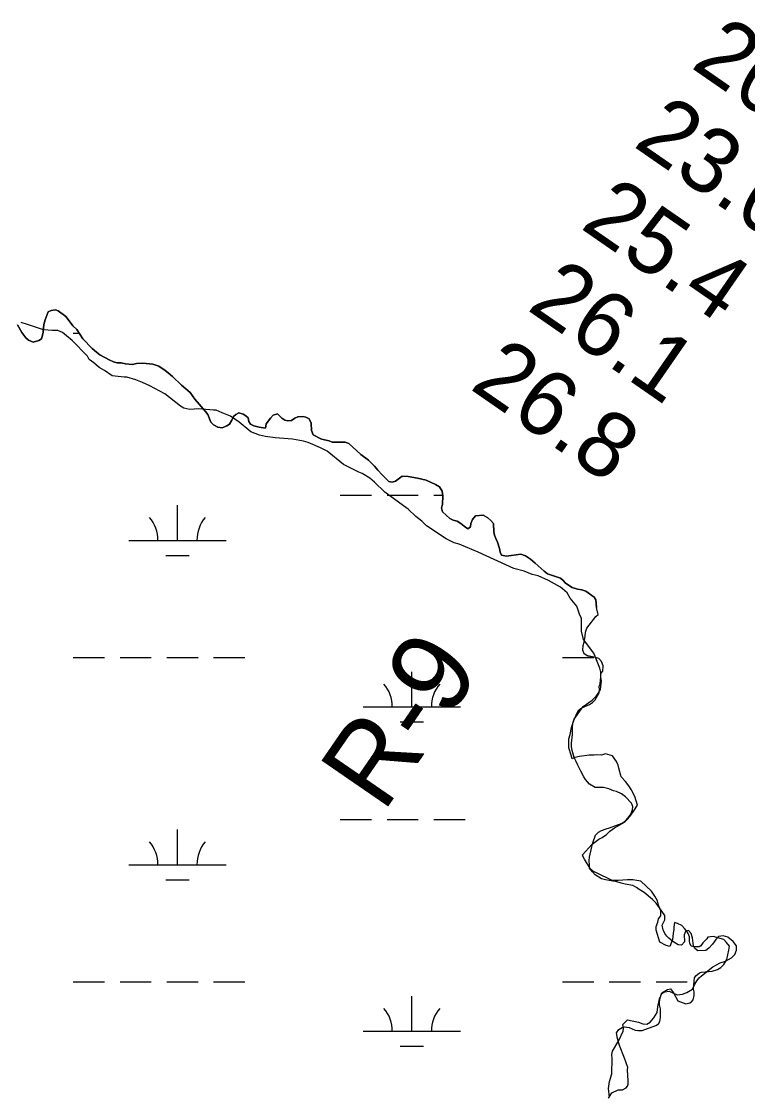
# Model space of a CAD drawing. Extents: x 3192927 to 3230760, y 831141 to 856475.
# Drawn here: x 3204190 to 3204934, y 850320 to 851421 of the extents above; entities that cross this region are included whole.
import ezdxf

# ---------------------------------------------------------------- set-up
doc = ezdxf.new("R2010")
doc.units = 0
for name, color, linetype in [('V-RIVR-RANG', 7, 'Continuous'), ('V-RIVR-RANG-IDEN', 7, 'Continuous'), ('V-SITE-VEGE', 7, 'Continuous'), ('V-TOPO-SHOR', 7, 'Continuous'), ('V-WETL-SWMP', 7, 'Continuous')]:
    doc.layers.add(name, color=color, linetype=linetype)

msp = doc.modelspace()

# ---------------------------------------------------------------- linework, layer by layer
at = {"layer": 'V-SITE-VEGE'}
for points in [[(3204356.3, 851024.6), (3204352.9, 851026.6), (3204336.8, 851039.5), (3204321.3, 851047.6), (3204313.8, 851051), (3204307.1, 851053.7), (3204297.7, 851056.4), (3204295, 851056.4), (3204282.8, 851057.8), (3204274.7, 851063.2), (3204269.4, 851066.5), (3204264, 851071.3), (3204259.2, 851074.7), (3204257.2, 851078), (3204241.7, 851094.2), (3204235.7, 851099), (3204231.6, 851102.4), (3204226.9, 851104.4), (3204221.5, 851104.4), (3204212.1, 851105.1), (3204195.9, 851110.5), (3204189.2, 851112.5)], [(3204799.1, 850540), (3204794.8, 850540.4), (3204780.2, 850547.7), (3204776.3, 850549.5), (3204772.9, 850552.5), (3204767.3, 850561.9), (3204765.6, 850564.5), (3204765.2, 850566.6), (3204775.1, 850577.4), (3204782, 850582.5), (3204785.4, 850584.2), (3204789.7, 850587.2), (3204793.1, 850590.6), (3204797.9, 850594.1), (3204808.2, 850600), (3204811.6, 850603.5), (3204814.6, 850607.3), (3204817.6, 850611.6), (3204821.5, 850617.6), (3204818.9, 850626.2), (3204815.1, 850633.5), (3204812.5, 850637.4), (3204809.1, 850641.7), (3204804.8, 850646.4), (3204802.2, 850655.4), (3204801.8, 850658.4), (3204800.1, 850662.3), (3204795.8, 850667.9), (3204788.5, 850670), (3204784.7, 850668.7), (3204779.5, 850669.2), (3204777, 850668.8), (3204771.8, 850668.8), (3204761.9, 850667.5), (3204757.2, 850666.2), (3204754.6, 850664.9), (3204753.4, 850668.8), (3204751.2, 850676.1), (3204751.2, 850685.5), (3204752.5, 850689.8), (3204753.8, 850697.1), (3204756.4, 850705.7), (3204765.9, 850718.5), (3204771.5, 850722.8), (3204774.9, 850725), (3204779.2, 850729.2), (3204781.3, 850731.8), (3204783.5, 850736.1), (3204783.9, 850739.1), (3204784.4, 850744.7), (3204783.9, 850748.6), (3204784, 850753.7), (3204782.7, 850758), (3204776.7, 850773.5), (3204766, 850787.2), (3204764, 850796), (3204764, 850808.8), (3204762, 850813.5), (3204759.3, 850821.6), (3204752.6, 850829.7), (3204749.2, 850835.1), (3204744.5, 850839.2), (3204742.5, 850841.2), (3204730.3, 850848), (3204719.5, 850852.7), (3204713.5, 850854.1), (3204705.4, 850857.4), (3204694.6, 850860.2), (3204658.2, 850877.1), (3204638.7, 850885.2), (3204633.3, 850886.6), (3204625.2, 850890.6), (3204605, 850904.1), (3204600.3, 850908.9), (3204594.2, 850913.6), (3204586.1, 850921), (3204581.4, 850924.4), (3204562.5, 850938.6), (3204551.8, 850948.7), (3204547, 850952.8), (3204539, 850957.5), (3204535.6, 850958.9), (3204520.1, 850967), (3204503.3, 850980.5), (3204496.5, 850983.9), (3204483.7, 850989.3), (3204479, 850990.7), (3204467.5, 850992.7), (3204450, 850994.1), (3204439.9, 850995.5), (3204433.8, 850996.8), (3204425, 851000.2), (3204423, 851002.2), (3204412.9, 851010.3), (3204404.2, 851016.4), (3204395.4, 851019.8), (3204389.3, 851022.5), (3204386.6, 851022.5), (3204371.1, 851023.9), (3204362.4, 851023.2), (3204356.3, 851024.6)], [(3204791.8, 850316.9), (3204795.3, 850322.4), (3204801.7, 850325.4), (3204806, 850325.4), (3204809.9, 850327.6), (3204811.2, 850329.3), (3204812, 850331.4), (3204812, 850334.8), (3204811.2, 850346), (3204811.6, 850348.2), (3204808.2, 850358), (3204803.1, 850370.9), (3204800.9, 850378.2), (3204800.1, 850383.8), (3204802.2, 850387.2), (3204805.7, 850389.4), (3204808.3, 850390.2), (3204813, 850389.3), (3204819, 850386.8), (3204822, 850386.3), (3204826.3, 850386.3), (3204840.4, 850391.4), (3204843, 850393.2), (3204844.3, 850395.7), (3204845.2, 850399.6), (3204845.2, 850408.6), (3204843.9, 850412.5), (3204843.9, 850415.5), (3204844.8, 850419.8), (3204846.5, 850424.9), (3204852.1, 850428.3), (3204855.5, 850429.2), (3204858.5, 850424.9), (3204862.8, 850416.7), (3204870.9, 850413.7), (3204875.2, 850414.6), (3204877, 850415.8), (3204878.7, 850417.6), (3204879.5, 850422.3), (3204879.5, 850426.1), (3204879.1, 850428.7), (3204879.6, 850436.9), (3204880, 850440.3), (3204881.3, 850442.4), (3204885.2, 850445.4), (3204887.3, 850446.3), (3204898, 850447.1), (3204903.6, 850448.8), (3204907.1, 850451), (3204910.1, 850454), (3204913.1, 850459.1), (3204915.2, 850468.6), (3204915.7, 850472.9), (3204912.7, 850476.7), (3204910.1, 850479.7), (3204899, 850482.8), (3204893.8, 850481.9), (3204892.5, 850480.2), (3204888.6, 850476.3), (3204886.5, 850473.3), (3204884.8, 850472), (3204879.2, 850472.1), (3204876.6, 850472.9), (3204875.3, 850475.9), (3204874.9, 850478.1), (3204874.9, 850482.4), (3204873.6, 850485.8), (3204871.9, 850488.4), (3204869.8, 850491), (3204866.8, 850494), (3204862.5, 850496.1), (3204859.5, 850497), (3204858.6, 850492.3), (3204858.6, 850490.1), (3204858.2, 850485.8), (3204857.3, 850479.8), (3204854.7, 850472.5), (3204850.9, 850473.4), (3204844.4, 850476.8), (3204840.6, 850489.3), (3204840.6, 850493.1), (3204842.3, 850497.4), (3204843.2, 850500.9), (3204845.3, 850503.9), (3204845.4, 850509), (3204843.2, 850515), (3204841.9, 850519.3), (3204839.4, 850524), (3204835.9, 850529.2), (3204824.8, 850539.5), (3204816.7, 850540.8), (3204811.1, 850540.8), (3204801.6, 850540), (3204799.1, 850540)]]:
    msp.add_lwpolyline(points, dxfattribs=at)
at = {"layer": 'V-TOPO-SHOR'}
for points in [[(3204185.6, 851110.2), (3204190, 851102.3), (3204194, 851096.7), (3204197, 851094.3), (3204201.7, 851092.2), (3204207.3, 851094.1), (3204210.1, 851095.9), (3204211.3, 851099.4), (3204212, 851102.5), (3204212.2, 851106.7), (3204212.7, 851110.6), (3204214.1, 851115.1), (3204217.1, 851123.5), (3204220, 851124.9), (3204224.4, 851125.6), (3204227.2, 851124.4), (3204235.1, 851118.8), (3204238.6, 851114.3), (3204242.3, 851109.2), (3204246.5, 851105.2), (3204252.4, 851095.9), (3204262.2, 851086), (3204266.6, 851082.1), (3204269.9, 851079.5), (3204279.7, 851074.1), (3204284.1, 851072.2), (3204287.8, 851071.3), (3204291.8, 851071.1), (3204296.2, 851070.1), (3204303.5, 851069.6), (3204307.7, 851070.3), (3204313.3, 851070.8), (3204317.5, 851070.5), (3204324.3, 851069.8), (3204330.6, 851067.7), (3204337.1, 851063.3), (3204340.1, 851060.9), (3204344.6, 851057.2), (3204353.9, 851048.1), (3204362.5, 851040.8), (3204367.6, 851033.8), (3204378.4, 851021.2), (3204380.7, 851018.1), (3204383.9, 851010.2), (3204386.7, 851007.4), (3204390.9, 851005.3), (3204395.4, 851004.3), (3204400.3, 851006.4), (3204403.1, 851008.3), (3204405.4, 851012.5), (3204407.1, 851016.2), (3204409.6, 851018.3), (3204412.5, 851019.7), (3204416.9, 851018.5), (3204419.7, 851016.9), (3204422, 851014.6), (3204423, 851010.8), (3204424.6, 851008.3), (3204428.1, 851006.6), (3204433.5, 851005.2), (3204440, 851004), (3204440.5, 851008.5), (3204444.9, 851014.3), (3204447.9, 851017.6), (3204452.4, 851019), (3204456.8, 851014.3), (3204459.6, 851012.2), (3204462.9, 851011.5), (3204466.6, 851011.9), (3204469.9, 851014.3), (3204473.2, 851015.9), (3204478.1, 851016.1), (3204481.3, 851015.4), (3204484.6, 851013.8), (3204486.9, 851009.3), (3204487.2, 851001.8), (3204488.8, 850997.4), (3204497.2, 850992.7), (3204505.1, 850991.1), (3204508.4, 850989.9), (3204516.8, 850989.9), (3204521.7, 850989.6), (3204525.4, 850988.5), (3204537.6, 850977), (3204545.5, 850971.2), (3204551.8, 850965.3), (3204555.3, 850961.1), (3204559.5, 850956.4), (3204566.5, 850949.4), (3204570, 850948.7), (3204573.2, 850949.6), (3204580, 850954.8), (3204586.3, 850954.5), (3204595.9, 850952.9)], [(3204595.9, 850952.9), (3204604.8, 850950.7), (3204614.3, 850946.3), (3204618.3, 850944), (3204621.1, 850939.5), (3204621.8, 850934.8), (3204621.6, 850926), (3204620.6, 850922.5), (3204621.5, 850918.3), (3204629, 850911.5), (3204632.5, 850909.8), (3204636.5, 850908.7), (3204640.4, 850906.3), (3204643.7, 850903.5), (3204647.4, 850900.9), (3204650.2, 850903), (3204650.7, 850906.5), (3204652.4, 850910.3), (3204655.2, 850914.2), (3204663.3, 850914.9), (3204668, 850912.3), (3204671, 850909.5), (3204673.8, 850906.5), (3204674.3, 850897.9), (3204674.7, 850894.4), (3204676.1, 850890.8), (3204678, 850887.1), (3204680.1, 850880.8), (3204680.6, 850877.1), (3204682, 850874), (3204687.1, 850872.8), (3204701.8, 850874.9), (3204706.5, 850873.3), (3204711.8, 850869.8), (3204716.5, 850865.8), (3204725.6, 850857.4), (3204729.3, 850854.6), (3204742.4, 850850.1), (3204745.4, 850847.8), (3204747.8, 850845), (3204754.5, 850840.7), (3204760.1, 850838.9), (3204764.3, 850838.4), (3204768.5, 850837), (3204776.9, 850830.7), (3204778.6, 850827.9), (3204779.5, 850820.2)], [(3204754.4, 850673.4), (3204753.8, 850677.3), (3204753.9, 850680.9), (3204754.8, 850690), (3204754.8, 850696.9), (3204755.3, 850701.5), (3204756.9, 850706), (3204759.2, 850711.4), (3204761.3, 850715.3), (3204764.3, 850717.4), (3204772.3, 850720.8), (3204775.3, 850722.7), (3204778, 850725.4), (3204782.2, 850732.6), (3204782.6, 850735.6), (3204782.2, 850739.1), (3204783.3, 850742), (3204784, 850749.2), (3204784, 850752.4), (3204785.8, 850754.9), (3204786.3, 850760.2), (3204784.4, 850764.9), (3204781.9, 850767.8), (3204778.4, 850769), (3204770.4, 850770.5), (3204766.9, 850772.8), (3204765.3, 850776.3), (3204765.7, 850781.1), (3204766.7, 850784.6), (3204767.8, 850790.4), (3204768.2, 850794.8), (3204769.4, 850798.9), (3204774.2, 850805.1), (3204776.2, 850807.9), (3204778.8, 850810.9), (3204781.1, 850812.9), (3204779.5, 850820.2)], [(3204822.5, 850394.7), (3204826.8, 850393.3), (3204831.2, 850392.8), (3204834.4, 850394.7), (3204838.4, 850399.3), (3204841.6, 850404.8), (3204842.5, 850410.6), (3204844.1, 850418.9), (3204846.4, 850424.2), (3204849.4, 850426.1), (3204853.9, 850426.7), (3204862.2, 850422.9), (3204867.6, 850423.5), (3204872.2, 850425.4), (3204877.9, 850428.8), (3204880.2, 850433.7), (3204882.5, 850437.4), (3204884.6, 850440.4), (3204887.1, 850442.5), (3204898.8, 850451.5), (3204906.4, 850455.8), (3204911.9, 850457.5), (3204917.9, 850460.7), (3204921.3, 850464.2), (3204923.2, 850468.6), (3204923.2, 850473.2), (3204919.7, 850477.5), (3204914.2, 850481.9), (3204909.5, 850483.5), (3204904.7, 850482.8), (3204901.8, 850479.6), (3204898.3, 850474.7), (3204894.8, 850470.8), (3204891.6, 850468.3), (3204883.3, 850468), (3204880.4, 850470.5), (3204879, 850473.1), (3204878, 850481.4), (3204876.4, 850485.9), (3204873.8, 850489), (3204870.6, 850488), (3204869.5, 850484.4), (3204869.8, 850477.4), (3204866.5, 850473.7), (3204863.3, 850474.2), (3204857.6, 850477.6), (3204853.8, 850480.9), (3204851.6, 850483.2), (3204849.7, 850485.9), (3204847.8, 850489.6), (3204846.7, 850494.4), (3204849.7, 850499.7), (3204849.4, 850504.1), (3204846.6, 850508.7), (3204840.6, 850517), (3204836.9, 850520.6), (3204828.2, 850527.8), (3204823.3, 850530.8), (3204820.3, 850533.1), (3204816.6, 850535.1), (3204808.8, 850536.5), (3204804.9, 850537.4), (3204799.1, 850539), (3204796.1, 850539.4), (3204788.8, 850541), (3204784.7, 850542), (3204778, 850545.9), (3204775.2, 850548.9), (3204772.2, 850552.7), (3204772.2, 850556), (3204771.9, 850560.8), (3204772.2, 850564.2), (3204774.5, 850574.8), (3204775.6, 850578.8), (3204778.5, 850586.8), (3204781.5, 850589.8), (3204784.5, 850591.4), (3204789.2, 850593.1), (3204792.8, 850594.2), (3204805.9, 850599.1), (3204809.6, 850601.6), (3204811.7, 850604), (3204814.5, 850608.1), (3204816.5, 850612.5), (3204816.7, 850616.2), (3204815.3, 850619.4), (3204809.3, 850626.1), (3204805, 850629), (3204799.9, 850631.5), (3204796.9, 850632.3), (3204792, 850634.1), (3204786.7, 850635.4), (3204778.2, 850635.6), (3204772.2, 850638.9), (3204768.3, 850643.7), (3204766.5, 850646.4), (3204763.5, 850652.4), (3204760.2, 850658.4), (3204758.1, 850662.8), (3204756.5, 850666.2), (3204754.4, 850673.4)], [(3204792.7, 850317.9), (3204791.8, 850326.7), (3204792.9, 850334), (3204795, 850341.7), (3204795.6, 850357.6), (3204795.1, 850361.7), (3204796, 850365.2), (3204802.2, 850376), (3204806.9, 850385.7), (3204807.1, 850388.7), (3204806.6, 850392.6), (3204811.4, 850397.2), (3204822.5, 850394.7)]]:
    msp.add_lwpolyline(points, dxfattribs=at)
at = {"layer": 'V-WETL-SWMP'}
for p, q in [((3204242.7, 851101.6), (3204248.7, 851101.6)), ((3204516.6, 850935.5), (3204548.6, 850935.5)), ((3204564.6, 850935.5), (3204596.6, 850935.5)), ((3204612.6, 850935.5), (3204621.7, 850935.5)), ((3204349.6, 850889), (3204349.6, 850925)), ((3204299.6, 850889), (3204399.6, 850889)), ((3204337.6, 850873.6), (3204361.6, 850873.6)), ((3204242.7, 850769), (3204274.7, 850769)), ((3204290.7, 850769), (3204322.7, 850769)), ((3204338.7, 850769), (3204370.7, 850769)), ((3204386.7, 850769), (3204418.7, 850769)), ((3204744.6, 850769), (3204776.6, 850769)), ((3204590, 850718.2), (3204590, 850754.2)), ((3204540, 850718.2), (3204640, 850718.2)), ((3204578, 850702.8), (3204602, 850702.8)), ((3204516.6, 850602.8), (3204548.6, 850602.8)), ((3204564.6, 850602.8), (3204596.6, 850602.8)), ((3204612.6, 850602.8), (3204644.6, 850602.8)), ((3204349.6, 850556.4), (3204349.6, 850592.4)), ((3204299.6, 850556.4), (3204399.6, 850556.4)), ((3204337.6, 850540.9), (3204361.6, 850540.9)), ((3204242.7, 850436.3), (3204274.7, 850436.3)), ((3204290.7, 850436.3), (3204322.7, 850436.3)), ((3204338.7, 850436.3), (3204370.7, 850436.3)), ((3204386.7, 850436.3), (3204418.7, 850436.3)), ((3204744.6, 850436.3), (3204776.6, 850436.3)), ((3204792.6, 850436.3), (3204824.6, 850436.3)), ((3204840.6, 850436.3), (3204872.6, 850436.3)), ((3204590, 850385.5), (3204590, 850421.5)), ((3204540, 850385.5), (3204640, 850385.5)), ((3204578, 850370.1), (3204602, 850370.1))]:
    msp.add_line(p, q, dxfattribs=at)
for points in [[(3204521.7, 850989.6), (3204516.8, 850989.9), (3204508.4, 850989.9), (3204505.1, 850991.1), (3204497.2, 850992.7), (3204488.8, 850997.4), (3204487.2, 851001.8), (3204486.9, 851009.3), (3204484.6, 851013.8), (3204481.3, 851015.4), (3204478.1, 851016.1), (3204473.2, 851015.9), (3204469.9, 851014.3), (3204466.6, 851011.9), (3204462.9, 851011.5), (3204459.6, 851012.2), (3204456.8, 851014.3), (3204452.4, 851019), (3204447.9, 851017.6), (3204444.9, 851014.3), (3204440.5, 851008.5), (3204440, 851004), (3204433.4, 851005.2), (3204428.1, 851006.6), (3204424.6, 851008.3), (3204422.9, 851010.8), (3204422, 851014.6), (3204419.7, 851016.9), (3204416.9, 851018.5), (3204412.5, 851019.7), (3204409.6, 851018.3), (3204407.1, 851016.2), (3204405.4, 851012.5), (3204403.1, 851008.3), (3204400.3, 851006.4), (3204395.4, 851004.3), (3204390.9, 851005.3), (3204386.7, 851007.4), (3204383.9, 851010.2), (3204380.7, 851018.1), (3204378.4, 851021.2), (3204367.6, 851033.8), (3204362.5, 851040.8), (3204353.9, 851048.1), (3204344.6, 851057.2), (3204340.1, 851060.9), (3204337.1, 851063.3), (3204330.6, 851067.7), (3204324.3, 851069.8), (3204317.5, 851070.5), (3204313.3, 851070.8), (3204307.7, 851070.3), (3204303.5, 851069.6), (3204296.2, 851070.1), (3204291.8, 851071.1), (3204287.8, 851071.3), (3204284.1, 851072.2), (3204279.7, 851074.1), (3204269.9, 851079.5), (3204266.6, 851082.1), (3204262.2, 851086), (3204252.4, 851095.9), (3204246.5, 851105.2), (3204242.3, 851109.2), (3204238.6, 851114.3), (3204235.1, 851118.8), (3204227.2, 851124.4), (3204224.4, 851125.6), (3204220, 851124.9), (3204217.1, 851123.5), (3204214.1, 851115.1), (3204212.7, 851110.6), (3204212.2, 851106.7), (3204212, 851102.5), (3204211.3, 851099.4), (3204210.1, 851095.9), (3204207.3, 851094.1), (3204201.7, 851092.2), (3204197, 851094.3), (3204194, 851096.7), (3204190, 851102.3), (3204185.6, 851110.2)], [(3204768.3, 850643.7), (3204766.5, 850646.4), (3204763.5, 850652.4), (3204760.2, 850658.4), (3204758.1, 850662.8), (3204756.5, 850666.2), (3204754.4, 850673.4), (3204753.8, 850677.3), (3204753.9, 850680.9), (3204754.8, 850690), (3204754.8, 850696.9), (3204755.3, 850701.5), (3204756.9, 850705.9), (3204759.2, 850711.4), (3204761.3, 850715.3), (3204764.3, 850717.4), (3204772.3, 850720.8), (3204775.3, 850722.7), (3204778, 850725.4), (3204782.2, 850732.6), (3204782.6, 850735.6), (3204782.2, 850739.1), (3204783.3, 850742), (3204784, 850749.2), (3204784, 850752.4), (3204785.8, 850754.9), (3204786.3, 850760.2), (3204784.4, 850764.9), (3204781.9, 850767.8), (3204778.4, 850769), (3204770.4, 850770.4), (3204766.9, 850772.8), (3204765.3, 850776.3), (3204765.7, 850781.1), (3204766.7, 850784.6), (3204767.8, 850790.4), (3204768.2, 850794.8), (3204769.4, 850798.9), (3204774.2, 850805.1), (3204776.2, 850807.9), (3204778.8, 850810.9), (3204781.1, 850812.9), (3204779.5, 850820.2), (3204778.6, 850827.9), (3204776.9, 850830.7), (3204768.5, 850837), (3204764.3, 850838.4), (3204760.1, 850838.9), (3204754.5, 850840.7), (3204747.8, 850845), (3204745.4, 850847.8), (3204742.4, 850850.1), (3204729.3, 850854.6), (3204725.6, 850857.4), (3204716.5, 850865.8), (3204711.8, 850869.8), (3204706.5, 850873.3), (3204701.8, 850874.9), (3204687.1, 850872.8), (3204682, 850874), (3204680.6, 850877.1), (3204680.1, 850880.8), (3204678, 850887.1), (3204676.1, 850890.8), (3204674.8, 850894.4), (3204674.3, 850897.9), (3204673.8, 850906.5), (3204671, 850909.5), (3204668, 850912.3), (3204663.3, 850914.9), (3204655.2, 850914.2), (3204652.4, 850910.3), (3204650.7, 850906.5), (3204650.2, 850903), (3204647.4, 850900.9), (3204643.7, 850903.5), (3204640.4, 850906.3), (3204636.5, 850908.7), (3204632.5, 850909.8), (3204629, 850911.5), (3204621.5, 850918.3), (3204620.6, 850922.5), (3204621.6, 850926), (3204621.8, 850934.8), (3204621.1, 850939.5), (3204618.3, 850944), (3204614.3, 850946.3), (3204604.8, 850950.7), (3204595.9, 850952.9), (3204586.3, 850954.5), (3204580, 850954.8), (3204573.2, 850949.6), (3204570, 850948.7), (3204566.5, 850949.4), (3204559.5, 850956.4), (3204555.3, 850961.1), (3204551.8, 850965.3), (3204545.5, 850971.2), (3204537.6, 850977), (3204525.4, 850988.5), (3204521.7, 850989.6)], [(3204796, 850365.2), (3204802.2, 850376), (3204806.9, 850385.7), (3204807.1, 850388.7), (3204806.6, 850392.6), (3204811.4, 850397.2), (3204822.5, 850394.7), (3204826.8, 850393.3), (3204831.2, 850392.8), (3204834.4, 850394.7), (3204838.4, 850399.3), (3204841.6, 850404.8), (3204842.5, 850410.6), (3204844.1, 850418.9), (3204846.4, 850424.2), (3204849.4, 850426.1), (3204853.9, 850426.7), (3204862.2, 850422.9), (3204867.6, 850423.5), (3204872.2, 850425.4), (3204877.9, 850428.8), (3204880.2, 850433.7), (3204882.5, 850437.4), (3204884.6, 850440.4), (3204887.1, 850442.5), (3204898.8, 850451.5), (3204906.4, 850455.8), (3204911.9, 850457.5), (3204917.9, 850460.7), (3204921.3, 850464.2), (3204923.2, 850468.6), (3204923.2, 850473.2), (3204919.7, 850477.5), (3204914.2, 850481.9), (3204909.5, 850483.5), (3204904.7, 850482.8), (3204901.8, 850479.6), (3204898.3, 850474.7), (3204894.8, 850470.8), (3204891.6, 850468.3), (3204883.3, 850468), (3204880.4, 850470.5), (3204879, 850473.1), (3204878, 850481.4), (3204876.4, 850485.9), (3204873.8, 850489), (3204870.6, 850488), (3204869.5, 850484.4), (3204869.8, 850477.4), (3204866.5, 850473.7), (3204863.3, 850474.2), (3204857.6, 850477.6), (3204853.8, 850480.9), (3204851.6, 850483.2), (3204849.7, 850485.9), (3204847.8, 850489.6), (3204846.7, 850494.4), (3204849.7, 850499.7), (3204849.4, 850504.1), (3204846.6, 850508.7), (3204840.6, 850517), (3204836.9, 850520.6), (3204828.2, 850527.8), (3204823.3, 850530.8), (3204820.3, 850533.1), (3204816.6, 850535.1), (3204808.8, 850536.5), (3204804.9, 850537.4), (3204799.1, 850539), (3204796.1, 850539.4), (3204788.8, 850541), (3204784.7, 850542), (3204778, 850545.9), (3204775.2, 850548.9), (3204772.2, 850552.7), (3204772.2, 850556), (3204771.9, 850560.8), (3204772.2, 850564.2), (3204774.5, 850574.8), (3204775.6, 850578.8), (3204778.5, 850586.8), (3204781.5, 850589.8), (3204784.5, 850591.4), (3204789.2, 850593.1), (3204792.8, 850594.2), (3204805.9, 850599.1), (3204809.6, 850601.6), (3204811.7, 850604), (3204814.5, 850608.1), (3204816.5, 850612.5), (3204816.7, 850616.2), (3204815.3, 850619.4), (3204809.3, 850626.1), (3204805, 850629), (3204799.9, 850631.5), (3204796.9, 850632.3), (3204792, 850634.1), (3204786.7, 850635.4), (3204778.2, 850635.6), (3204772.2, 850638.9), (3204768.3, 850643.7)], [(3204792.7, 850317.9), (3204791.8, 850326.7), (3204792.9, 850334), (3204795, 850341.7), (3204795.6, 850357.6), (3204795.1, 850361.7), (3204796, 850365.2)]]:
    msp.add_lwpolyline(points, dxfattribs=at)
for centre, start, end in [((3204294.3, 850889.5), 359.2282, 40.7718), ((3204404.8, 850889.5), 139.2282, 180.7718), ((3204534.8, 850718.7), 359.2282, 40.7718), ((3204645.3, 850718.7), 139.2282, 180.7718), ((3204294.3, 850556.8), 359.2282, 40.7718), ((3204404.8, 850556.8), 139.2282, 180.7718), ((3204534.8, 850386), 359.2282, 40.7718), ((3204645.3, 850386), 139.2282, 180.7718)]:
    msp.add_arc(centre, 35.2, start, end, dxfattribs=at)

# ---------------------------------------------------------------- texts
at = {"layer": 'V-RIVR-RANG'}
for s, p in [('20.8', (3204874.9, 851374.8)), ('23.0', (3204815.9, 851294)), ('25.4', (3204761.6, 851210)), ('26.1', (3204706.9, 851126.3)), ('26.8', (3204648.2, 851045.2))]:
    msp.add_text(s, height=67, rotation=325.3283, dxfattribs=at).set_placement(p)
at = {"layer": 'V-RIVR-RANG-IDEN'}
msp.add_text('R-9', height=83, rotation=55.4727, dxfattribs=at).set_placement((3204560.6, 850608.6))

doc.saveas('drawing.dxf')
